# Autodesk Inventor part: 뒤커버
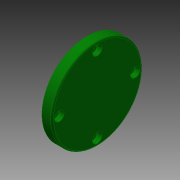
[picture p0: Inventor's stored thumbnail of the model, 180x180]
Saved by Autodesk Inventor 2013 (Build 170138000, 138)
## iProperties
Created: 2015-09
Part Number: 뒤커버
Material: 알루미늄 6061
Document SubType Name: Modeling
Designer: mduedu
Density: 2.71 g/cm^3
Mass: 54.0417 g
Surface Area: 84.9688 cm^2
Volume: 19.9416 cm^3
Author: mduedu
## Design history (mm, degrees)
sketch "스케치1"
  geometry: L1 (-15.5, 47)-(-15.5, 78); L2 (-15.5, 78)-(-22.5, 78); L3 (-22.5, 78)-(-22.5, 67); L4 (-25.5, 67)-(-25.5, 47); L5 (-79.5, 39.5)-(-79.5, 54.5) reference; L6 (48.5, 54.5)-(48.5, 39.5) reference; L7 (-79.5, 47)-(48.5, 47); L8 (-22.5, 67)-(-25.5, 67); L9 (-25.5, 47)-(-15.5, 47); 1 further point
  constraints: 14 end point, 4 midpoint, 3 parallel, 1 collinear, 1 point on line, 1 vertical
  dimensions: "d6" = 62 diameter of L2 L7; "d7" = 7 distance of L1.end L2.end; "d8" = 40 diameter of L3.end L7; "d32" = 10 distance between parallel lines of L1 L4
revolve "회전1" sketch "스케치1" stored, may be unused: angle "d4" = 90 deg
sketch "스케치4"
  geometry: C1 r 31 at (0, 0) reference; 2 further points
  constraints: 1 coincident
hole "구멍3" sketch "스케치4" at (0, 0) diameter "d33" = 33; stored, may be unused: countersink angle "d37" = 90 deg, drill point angle "d39" = 0 deg; dims "d34" = 6, "d35" = 4, "d36" = 2, "d38" = 5
fillet "모깎기4" dims "d40" = 1, "d61" = 3
chamfer "모따기2" distance "d41" = 1; stored, may be unused: second distance "d42" = 2, angle "d43" = 45 deg
sketch "스케치6" dims "d56" = 52
  geometry: C1 r 31 at (0, 0) reference; 5 further points
  constraints: 2 vertical alignment, 1 coincident, 7 other
  dimensions: "d59" = 360 deg dimension on C1.centre point (0, 26) (derived)
hole "구멍4" sketch "스케치6" at (0, 26), (-26, 0), (0, -26), (26, 0) diameter "d49" = 3.4; stored, may be unused: countersink angle "d53" = 90 deg, drill point angle "d55" = 0 deg; dims "d50" = 6, "d51" = 6.5, "d52" = 3.4, "d54" = 8
node "솔리드1"
node "참조1"
node "참조2"
